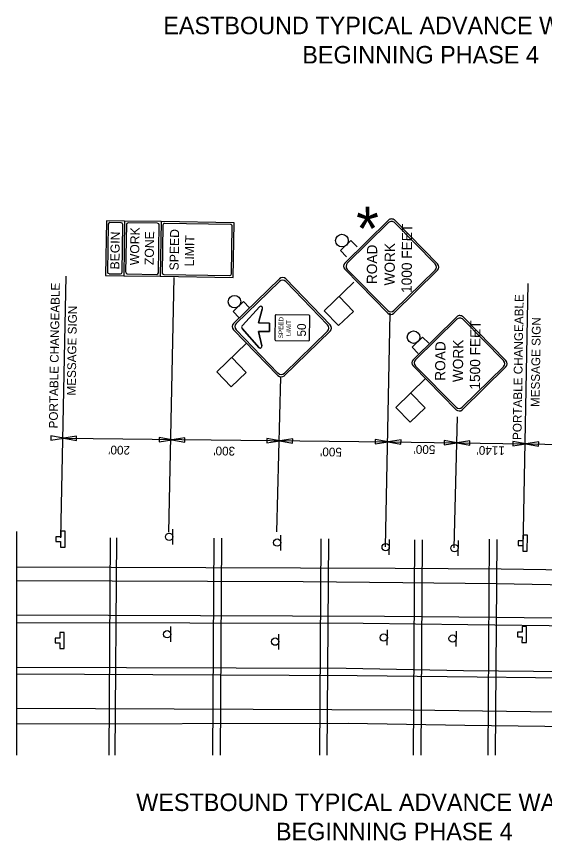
# Model space of a CAD drawing. Extents: x 2155255 to 2162649, y 140388 to 141878.
# Drawn here: x 2158340 to 2158702, y 140577 to 141142 of the extents above; entities that cross this region are included whole.
import ezdxf

# ---------------------------------------------------------------- set-up
doc = ezdxf.new("R2010")
doc.units = 0
for name, color, linetype in [('5', 7, 'Continuous'), ('Default', 7, 'Continuous'), ('PR_Align_CRL_Txt', 7, 'Continuous'), ('PR_Dimensions', 7, 'Continuous'), ('PR_Dimensions_Phase4', 7, 'Continuous'), ('PR_Traffic_Control_Devices_Temp', 7, 'Continuous'), ('PR_Traffic_Control_Devices_Temp_Ph4', 7, 'Continuous'), ('SHT_Match_Lines', 7, 'Continuous'), ('T_PHASE_4', 7, 'Continuous'), ('TOPO_Asphalt', 7, 'Continuous')]:
    doc.layers.add(name, color=color, linetype=linetype)

# ---------------------------------------------------------------- blocks, each defined once
blk = doc.blocks.new('Arrowhd')
at = {"layer": 'Default'}
blk.add_lwpolyline([(0.318, -0.053), (0.318, 0.053), (0, 0)], close=True, dxfattribs=at)
blk = doc.blocks.new('PR-TCSIGN')
at = {"layer": 'Default'}
blk.add_line((17.8, 8.5), (-17.8, 8.5), dxfattribs=at)
blk.add_circle((0, 0), 8.47, dxfattribs=at)
blk = doc.blocks.new('FLSHFLAG')
at = {"layer": 'Default'}
for p, q in [((-1.2, 14.13), (0.84, 16.15)), ((0.84, 16.15), (4.9, 12.08)), ((0.82, 12.08), (-1.2, 14.13)), ((0.82, 12.08), (2.86, 14.11)), ((9.26, 14), (8.4, 13.15)), ((9.26, 14), (10.68, 12.58)), ((10.68, 12.58), (9.83, 11.72))]:
    blk.add_line(p, q, dxfattribs=at)
blk.add_circle((10.65, 13.84), 0.873, dxfattribs=at)
blk = doc.blocks.new('CS-13E')
at = {"layer": 'Default'}
for p, q in [((0, 2.54), (0, 0)), ((7.62, 2.54), (0, 2.54)), ((7.62, 0), (7.62, 2.54)), ((0.25, 2.06), (0.25, 0.48)), ((7.14, 2.29), (0.48, 2.29)), ((7.37, 0.48), (7.37, 2.06)), ((7.62, 0), (0, 0)), ((0.48, 0.25), (7.14, 0.25))]:
    blk.add_line(p, q, dxfattribs=at)
for centre, start, end in [((0.48, 2.06), 90, 180), ((7.14, 2.06), 0, 90), ((0.48, 0.48), 180, 270), ((7.14, 0.48), 270, 0)]:
    blk.add_arc(centre, 0.222, start, end, dxfattribs=at)
blk.add_text('BEGIN', height=1.27, dxfattribs=at).set_placement((0.85, 0.64))
blk = doc.blocks.new('R2-1E_2')
at = {"layer": 'Default'}
for p, q in [((7.62, 10.16), (0, 10.16)), ((0, 10.16), (0, 0)), ((0.25, 9.68), (0.25, 0.48)), ((7.14, 9.91), (0.48, 9.91)), ((7.37, 0.48), (7.37, 9.68)), ((7.62, 0), (7.62, 10.16)), ((0, 0), (7.62, 0)), ((0.48, 0.25), (7.14, 0.25))]:
    blk.add_line(p, q, dxfattribs=at)
for centre, start, end in [((0.48, 9.68), 90, 180), ((7.14, 9.68), 0, 90), ((0.48, 0.48), 180, 270), ((7.14, 0.48), 270, 0)]:
    blk.add_arc(centre, 0.222, start, end, dxfattribs=at)
for s, p in [('SPEED', (0.85, 7.62)), ('LIMIT', (1.44, 5.5))]:
    blk.add_text(s, height=1.27, dxfattribs=at).set_placement(p)
blk = doc.blocks.new('CS-14E')
at = {"layer": 'Default'}
for p, q in [((7.62, 2.54), (0, 2.54)), ((0, 2.54), (0, -2.54)), ((7.62, -2.54), (7.62, 2.54)), ((0.25, 2.06), (0.25, -2.06)), ((7.14, 2.29), (0.48, 2.29)), ((7.37, -2.06), (7.37, 2.06)), ((0.48, -2.29), (7.14, -2.29)), ((7.62, -2.54), (0, -2.54))]:
    blk.add_line(p, q, dxfattribs=at)
for centre, start, end in [((0.48, 2.06), 90, 180), ((7.14, 2.06), 0, 90), ((0.48, -2.06), 180, 270), ((7.14, -2.06), 270, 0)]:
    blk.add_arc(centre, 0.222, start, end, dxfattribs=at)
for s, p in [('WORK', (1.48, 0.44)), ('ZONE', (1.53, -1.6))]:
    blk.add_text(s, height=1.27, dxfattribs=at).set_placement(p)
blk = doc.blocks.new('W3-5_2')
at = {"layer": '5'}
for p, q in [((0.81, 7.63), (6.73, 13.56)), ((13.56, 7.63), (7.63, 13.56)), ((6.73, 0.81), (0.81, 6.74)), ((7.63, 0.81), (13.56, 6.74))]:
    blk.add_line(p, q, dxfattribs=at)
for centre, start, end in [((7.18, 13.11), 45, 135), ((1.26, 7.18), 135, 225), ((13.11, 7.18), 315, 45), ((7.18, 1.26), 225, 315)]:
    blk.add_arc(centre, 0.635, start, end, dxfattribs=at)
at = {"layer": 'Default'}
for p, q in [((0.45, 7.63), (6.73, 13.92)), ((13.92, 7.63), (7.63, 13.92)), ((6.95, 12.72), (4.28, 10.3)), ((9.98, 10.32), (7.37, 12.69)), ((8.8, 8.13), (5.46, 8.13)), ((5.35, 8.02), (5.35, 3.42)), ((8.91, 3.42), (8.91, 8.02)), ((6.73, 0.45), (0.45, 6.74)), ((7.63, 0.45), (13.92, 6.74)), ((5.46, 3.3), (8.8, 3.3))]:
    blk.add_line(p, q, dxfattribs=at)
for points in [[(4.28, 10.3), (6.95, 12.72)], [(7.37, 12.69), (9.98, 10.32)], [(4.58, 9.92), (6.55, 10.41), (6.55, 8.91), (7.74, 8.91), (7.74, 10.45), (9.68, 9.96)], [(9.68, 9.96), (7.74, 10.45), (7.74, 8.91), (6.55, 8.91), (6.55, 10.41), (4.58, 9.92)]]:
    blk.add_lwpolyline(points, dxfattribs=at)
for centre, radius, start, end in [((7.18, 13.47), 0.635, 45, 135), ((7.14, 12.51), 0.285, 37.9142, 132.1493), ((7.14, 12.51), 0.285, 37.9142, 132.1493), ((4.52, 10.19), 0.269, 154.0903, 283.9085), ((4.52, 10.19), 0.269, 154.0903, 283.9085), ((9.83, 10.15), 0.237, 231.3417, 47.9123), ((9.83, 10.15), 0.237, 231.3417, 47.9123), ((5.46, 8.02), 0.111, 90, 180), ((8.8, 8.02), 0.111, 0, 90), ((0.9, 7.18), 0.635, 135, 225), ((13.47, 7.18), 0.635, 315, 45), ((5.46, 3.42), 0.111, 180, 270), ((8.8, 3.42), 0.111, 270, 0), ((7.18, 0.9), 0.635, 225, 315)]:
    blk.add_arc(centre, radius, start, end, dxfattribs=at)
for s, p in [('SPEED', (5.65, 6.99)), ('LIMIT', (5.95, 5.93))]:
    blk.add_text(s, height=0.635, dxfattribs=at).set_placement(p)
blk = doc.blocks.new('Cw20-1_none')
at = {"layer": 'Default'}
for p, q in [((0.177, 3.005), (2.651, 5.48)), ((0.318, 3.005), (2.651, 5.339)), ((5.48, 3.005), (3.005, 5.48)), ((5.338, 3.005), (3.005, 5.339)), ((2.651, 0.177), (0.177, 2.652)), ((2.651, 0.318), (0.318, 2.652)), ((3.005, 0.177), (5.48, 2.652)), ((3.005, 0.318), (5.338, 2.652))]:
    blk.add_line(p, q, dxfattribs=at)
for centre, start, end in [((2.828, 5.303), 45, 135), ((2.828, 5.162), 45, 135), ((0.353, 2.828), 135, 225), ((0.495, 2.828), 135, 225), ((5.162, 2.828), 315, 45), ((5.303, 2.828), 315, 45), ((2.828, 0.495), 225, 315), ((2.828, 0.354), 225, 315)]:
    blk.add_arc(centre, 0.25, start, end, dxfattribs=at)
for s, p in [('ROAD', (1.821, 3.637)), ('WORK', (1.751, 2.623))]:
    blk.add_text(s, height=0.5833, dxfattribs=at).set_placement(p)
blk = doc.blocks.new('PR-TCSIGN_rev')
at = {"layer": 'Default'}
blk.add_lwpolyline([(-5.47, 0), (-1.58, 0), (-1.58, -3.22), (1.58, -3.22), (1.58, 0), (5.47, 0), (5.47, 3.06), (-5.47, 3.06)], close=True, dxfattribs=at)
blk.add_lwpolyline([(1.58, 0), (5.47, 0), (5.47, 3.06), (-5.47, 3.06), (-5.47, 0), (-1.58, 0), (-1.58, -3.22), (1.58, -3.22), (1.58, 0)], dxfattribs=at)

msp = doc.modelspace()

# ---------------------------------------------------------------- linework, layer by layer
at = {"layer": 'PR_Dimensions'}
for p, q in [((2158403.69, 140784.35), (2158402.74, 140635.4)), ((2158407.99, 140784.32), (2158407.04, 140635.4)), ((2158474.91, 140784.13), (2158473.96, 140635.4)), ((2158480.08, 140784.1), (2158479.14, 140635.4)), ((2158548.17, 140783.61), (2158547.23, 140635.4)), ((2158553.34, 140783.58), (2158552.4, 140635.4)), ((2158612.51, 140782.96), (2158611.57, 140635.4)), ((2158617.69, 140782.92), (2158616.75, 140635.4)), ((2158663.6, 140783.27), (2158662.66, 140635.4)), ((2158668.77, 140783.24), (2158667.83, 140635.4))]:
    msp.add_line(p, q, dxfattribs=at)
at = {"layer": 'PR_Dimensions_Phase4'}
for p, q in [((2158369.92, 140784.22), (2158373.55, 140963.65)), ((2158443.96, 140788.13), (2158447.55, 140962.72)), ((2158686.84, 140777.24), (2158690.45, 140958.64)), ((2158592.44, 140778.05), (2158595.72, 140938.17)), ((2158517.96, 140788.27), (2158520.69, 140894.41)), ((2158639.64, 140777.38), (2158641.86, 140867.13)), ((2158371.87, 140852.6), (2158594.39, 140850.07)), ((2158594.39, 140850.07), (2158641.59, 140849.36)), ((2158641.59, 140849.36), (2158688.79, 140848.65)), ((2158688.79, 140848.65), (2158738.78, 140847.89))]:
    msp.add_line(p, q, dxfattribs=at)
at = {"layer": 'SHT_Match_Lines'}
msp.add_line((2158339.5, 140788.6), (2158339.5, 140635.4), dxfattribs=at)
at = {"layer": 'TOPO_Asphalt'}
for points in [[(2158985.45, 140758.34), (2158954.84, 140758.64), (2158891.69, 140760.05), (2158823.37, 140760.54), (2158748.49, 140761.6), (2158671.86, 140762.77), (2158599.2, 140763.25), (2158339.5, 140764.15)], [(2158339.5, 140755.13), (2158536.13, 140754.45), (2158604.42, 140753.64), (2158668.32, 140752.87), (2158742.44, 140751.71), (2158814.74, 140750.49), (2158890.81, 140749.51), (2158962.3, 140748.71), (2158985.31, 140748.39)], [(2158984.98, 140725.3), (2158961.37, 140725.72), (2158896.27, 140726.46), (2158818.27, 140727.49), (2158746.18, 140728.67), (2158668.15, 140729.7), (2158591.81, 140730.44), (2158339.5, 140731.37)], [(2158339.5, 140726.26), (2158577.15, 140725.89), (2158648.99, 140724.76), (2158723.3, 140724.05), (2158797.25, 140723.18), (2158864.83, 140722.4), (2158947.82, 140721.54), (2158984.92, 140720.89)], [(2158984.46, 140689.26), (2158944.19, 140689.59), (2158869.07, 140690.59), (2158789.58, 140691.75), (2158717.96, 140692.35), (2158646.13, 140693.06), (2158565.61, 140694.65), (2158339.5, 140695.44)], [(2158339.5, 140690.94), (2158573, 140690.01), (2158655.33, 140689.09), (2158735.4, 140688.13), (2158817.72, 140687.16), (2158901.17, 140686.17), (2158980.56, 140685.01), (2158984.4, 140684.97)], [(2158984.07, 140661.58), (2158946.06, 140661.94), (2158862.52, 140663), (2158780.1, 140664.3), (2158691.97, 140665.01), (2158610.02, 140666.17), (2158339.5, 140667.26)], [(2158339.5, 140656.87), (2158567.01, 140657.15), (2158647.04, 140655.81), (2158738.29, 140654.81), (2158820.78, 140653.93), (2158906.91, 140652.62), (2158974.15, 140651.69), (2158983.92, 140651.46)]]:
    msp.add_lwpolyline(points, dxfattribs=at)

# ---------------------------------------------------------------- block references
at = {"layer": 'PR_Dimensions_Phase4'}
for p, xscale, yscale, rotation in [((2158371.78, 140852.58), 27.558999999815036, 27.55899999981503, 179.13349017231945), ((2158371.78, 140852.58), 27.559000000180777, 27.55900000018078, 179.13349016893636), ((2158371.87, 140852.6), 27.559000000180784, 27.559000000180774, -0.8665098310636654), ((2158446.05, 140851.36), 27.559000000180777, 27.55900000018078, 179.13349016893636), ((2158446.14, 140851.37), 27.559000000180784, 27.559000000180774, -0.8665098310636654), ((2158520.02, 140850.71), 27.559000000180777, 27.55900000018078, 179.13349016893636), ((2158520.12, 140850.72), 27.559000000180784, 27.559000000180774, -0.8665098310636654), ((2158594.3, 140850.06), 27.559000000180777, 27.55900000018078, 179.13349016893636), ((2158594.39, 140850.07), 27.559000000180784, 27.559000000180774, -0.8665098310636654), ((2158641.49, 140849.35), 27.559000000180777, 27.55900000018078, 179.13349016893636), ((2158641.59, 140849.36), 27.559000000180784, 27.559000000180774, -0.8665098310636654), ((2158688.69, 140848.63), 27.559000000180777, 27.55900000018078, 179.13349016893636), ((2158688.79, 140848.65), 27.559000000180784, 27.559000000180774, -0.8665098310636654)]:
    msp.add_blockref('Arrowhd', p, dxfattribs=dict(at, xscale=xscale, yscale=yscale, rotation=rotation))
at = {"layer": 'PR_Traffic_Control_Devices_Temp_Ph4'}
for name, p, xscale, yscale, rotation in [('CS-13E', (2158413.11, 140963.93), 4.92124999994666, 4.921249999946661, 89.13349015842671), ('CS-14E', (2158425.6, 140963.74), 4.921249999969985, 4.9212499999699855, 89.1334901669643), ('R2-1E_2', (2158488.1, 140962.79), 4.92125000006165, 4.92125000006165, 89.1334901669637), ('Cw20-1_none', (2158630.1, 140935.92), 12, 12, 89.4985074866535), ('FLSHFLAG', (2158629.97, 140934.58), 4.92125000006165, 4.92125000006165, 89.1334901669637), ('W3-5_2', (2158556.28, 140892.69), 4.92125000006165, 4.92125000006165, 89.1334901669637), ('FLSHFLAG', (2158556.28, 140892.69), 4.92125000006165, 4.92125000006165, 89.1334901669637), ('Cw20-1_none', (2158676.94, 140869.67), 12, 12, 89.4985074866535), ('FLSHFLAG', (2158679.09, 140868.36), 4.92125000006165, 4.92125000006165, 89.1334901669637), ('PR-TCSIGN', (2158444.19, 140784.98), 0.29527500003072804, 0.2952750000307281, -90.86650983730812), ('PR-TCSIGN', (2158518.28, 140780.99), 0.29527500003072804, 0.2952750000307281, -90.86650983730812), ('PR-TCSIGN', (2158592.65, 140777.86), 0.29527500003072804, 0.2952750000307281, -90.86650983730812), ('PR-TCSIGN', (2158639.9, 140777.15), 0.29527500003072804, 0.2952750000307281, -90.86650983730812), ('PR-TCSIGN', (2158442.81, 140718.18), 0.29527500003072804, 0.2952750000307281, -90.86650983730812), ('PR-TCSIGN', (2158516.88, 140713.12), 0.29527500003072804, 0.2952750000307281, -90.86650983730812), ('PR-TCSIGN', (2158591.31, 140715.9), 0.29527500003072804, 0.2952750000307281, -90.86650983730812), ('PR-TCSIGN', (2158638.55, 140715.19), 0.29527500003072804, 0.2952750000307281, -90.86650983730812)]:
    msp.add_blockref(name, p, dxfattribs=dict(at, xscale=xscale, yscale=yscale, rotation=rotation))
at = {"layer": 'PR_Traffic_Control_Devices_Temp_Ph4', "rotation": -90.50149251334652}
for p in [(2158369.8, 140783.41), (2158686.72, 140780.64), (2158686.17, 140717.98), (2158369.19, 140713.91)]:
    msp.add_blockref('PR-TCSIGN_rev', p, dxfattribs=at)

# ---------------------------------------------------------------- texts
at = {"layer": 'PR_Align_CRL_Txt'}
for s, p in [('EASTBOUND TYPICAL ADVANCE WARNING', (2158440.15, 141129.43)), ('BEGINNING PHASE 4', (2158535.47, 141109.39)), ('WESTBOUND TYPICAL ADVANCE WARNING', (2158421.59, 140597.01)), ('BEGINNING PHASE 4', (2158517.43, 140576.97))]:
    msp.add_text(s, height=12, dxfattribs=at).set_placement(p)
at = {"layer": 'PR_Traffic_Control_Devices_Temp'}
msp.add_text('*', height=30, dxfattribs=at).set_placement((2158572.38, 140981.26))
at = {"layer": 'PR_Traffic_Control_Devices_Temp_Ph4'}
for s, height, p in [('1000 FEET', 7, (2158610.46, 140952.11)), ('50', 6, (2158537.96, 140922.24)), ('1500 FEET', 7, (2158657.3, 140885.85))]:
    msp.add_text(s, height=height, rotation=89.4985, dxfattribs=at).set_placement(p)
at = {"layer": 'T_PHASE_4'}
for s, rotation, p in [('PORTABLE CHANGEABLE', 89.1335, (2158367.73, 140859.2)), ('PORTABLE CHANGEABLE', 89.1335, (2158685.75, 140851.31)), ('MESSAGE SIGN', 89.1335, (2158380.07, 140881.78)), ('MESSAGE SIGN', 89.1335, (2158698.1, 140873.88)), ("200'", 179.1335, (2158417.39, 140847.26)), ("300'", 179.1335, (2158489.46, 140846.63)), ("500'", 179.1335, (2158562.67, 140845.99)), ("500'", 179.1335, (2158626.77, 140847.69)), ("1140'", 179.1335, (2158674.41, 140846.97))]:
    msp.add_text(s, height=6, rotation=rotation, dxfattribs=at).set_placement(p)

doc.saveas('drawing.dxf')
